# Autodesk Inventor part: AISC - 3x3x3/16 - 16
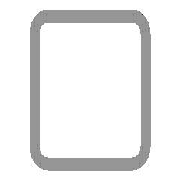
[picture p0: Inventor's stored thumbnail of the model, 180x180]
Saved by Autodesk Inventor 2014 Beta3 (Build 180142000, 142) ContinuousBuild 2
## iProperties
IsCustomPart: 1
_CCFamilyMember: 9
_CCFamilyDisplayName: ANSI AISC (Square) - Tube
_FrameMemberDoc: Frame Member File
_Version: 15.0.0
_GetPNFromCC: 1
Created: 2010-11
Part Number: AISC - 3x3x3/16 - 16
Material: Steel, Mild
Description: Tube
Document SubType Name: Modeling
Standard: ANSI
Designer: Beta-8540w
Standards Organization: ANSI
Language: en-US
Size Designation: 3x3x3/16
Categories: <MemberInstance><Categories><Category DisplayName="Structural Shapes" InternalName="089c4875-fa83-4c05-b084-43b9cc11f5ed" Mnemonic="GRDR"><CategoryParameter Dis
Stock Number: 3x3x3/16
Density: 7.86 g/cm^3
Appearance: Steel
G_L: 16.000 in
G_W: 3.000 in
G_H: 3.000 in
Author: Beta-8540w
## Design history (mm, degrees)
node "Start plane"
node "End plane"
sketch "Sketch"
  geometry: L1 (-38.1, -28.575)-(-38.1, 28.575); L2 (-28.575, 38.1)-(28.575, 38.1); L3 (38.1, 28.575)-(38.1, -28.575); L4 (28.575, -38.1)-(-28.575, -38.1); L5 (-28.575, 33.337)-(28.575, 33.338); L6 (33.338, 28.575)-(33.338, -28.575); L7 (28.575, -33.337)-(-28.575, -33.338); L8 (-33.338, -28.575)-(-33.338, 28.575); L9 (0, 56.102)-(0, -56.102) reference; L10 (-56.102, 0)-(56.102, 0) reference; A1 r 9.525 centre (-28.575, -28.575) between (-38.1, -28.575) and (-28.575, -38.1); A2 r 9.525 centre (-28.575, 28.575) between (-28.575, 38.1) and (-38.1, 28.575); A3 r 9.525 centre (28.575, 28.575) between (38.1, 28.575) and (28.575, 38.1); A4 r 9.525 centre (28.575, -28.575) between (28.575, -38.1) and (38.1, -28.575); A5 r 4.763 centre (-28.575, 28.575) between (-28.575, 33.337) and (-33.338, 28.575); A6 r 4.763 centre (28.575, 28.575) between (33.338, 28.575) and (28.575, 33.338); A7 r 4.763 centre (28.575, -28.575) between (28.575, -33.337) and (33.338, -28.575); A8 r 4.763 centre (-28.575, -28.575) between (-33.338, -28.575) and (-28.575, -33.338)
  constraints: 16 end point, 16 point on circle, 8 centre point, 8 tangent, 4 parallel, 3 equal radius, 2 perpendicular, 7 other
  dimensions: "d10" = 76.2 distance between parallel lines of L2 L4 (= G_H); "d11" = 76.2 distance between parallel lines of L1 L3 (= G_W); "d12" = 4.7625 distance between parallel lines of L3 L6 (= G_T); "d15" = 38.1 distance between parallel lines of L2 L10 (= 0.5 x d10); "d16" = 38.1 distance between parallel lines of L9 L3 (= 0.5 x d11); "d17" = 9.525 radius of A1 (= G_IR)
extrude "Body" new body sketch "Sketch" stored distance "d3" = 406.4 (= G_L); taper "d4" = 0 deg
node "Driven Length"
  sketch "Sketch3"
    geometry: L1 (0, 0)-(10, 0) reference
    constraints: 2 end point, 1 horizontal
  workplane "Work Plane3"
  sketch "Sketch4"
    geometry: L1 (-2, -114.3)-(12, -114.3) reference; L2 (-2, 292.1)-(12, 292.1) reference
    dimensions: "d19" = 406.4 distance between parallel lines of L1 L2 (derived)
workplane "Work Plane4"
split "Split1"
body "Solid1"
other parameters: "G_W" = 76.2 [user parameter; used in 1 equation term], "G_H" = 76.2 [user parameter; used in 1 equation term], "G_T" = 4.7625 [user parameter; used in 1 equation term], "G_IR" = 9.525 [user parameter; used in 1 equation term], "G_L" = 406.4 (= d19) [user parameter; used in 1 equation term], "G_OFFSET_START" = 114.3 [user parameter; used in 1 equation term], "G_OFFSET_END" = 38.1 [user parameter; used in 1 equation term], "d13" = -114.3 (= -G_OFFSET_START), "d14" = 292.1 (= G_OFFSET_END + B_L), "B_L" = 254 [user parameter; used in 1 equation term], "d18" = 90 deg
